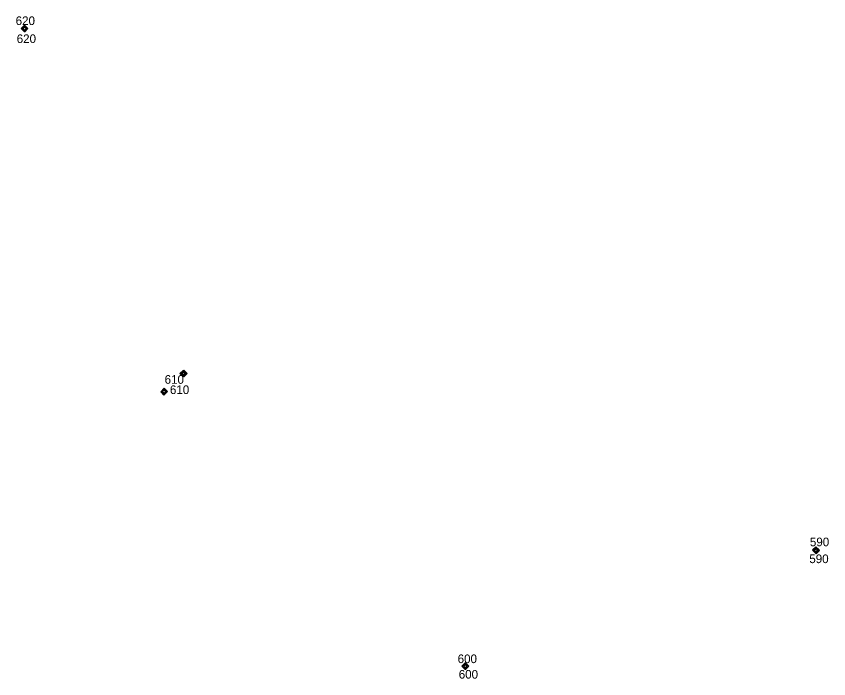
# Model space of a CAD drawing. Extents: x 3461750 to 3585707, y 5917729 to 5985917.
# Drawn here: x 3566933 to 3585707, y 5919226 to 5934529 of the extents above; entities that cross this region are included whole.
import ezdxf

# ---------------------------------------------------------------- set-up
doc = ezdxf.new("R2010")
doc.units = 0
doc.header["$LTSCALE"] = 80
doc.layers.add('13', color=7, linetype='Continuous', lineweight=13)
doc.layers.add('14', color=7, linetype='Continuous', lineweight=13)

msp = doc.modelspace()

# ---------------------------------------------------------------- linework, layer by layer
at = {"layer": '13'}
for points in [[(3567129.33, 5934317.19), (3567054.24, 5934242.1), (3567129.33, 5934167.01), (3567204.42, 5934242.1)], [(3567129.33, 5934281.79), (3567089.64, 5934242.1), (3567129.33, 5934202.41), (3567169.02, 5934242.1)], [(3570804.92, 5926351.18), (3570729.82, 5926276.09), (3570804.92, 5926201), (3570880.01, 5926276.09)], [(3570804.92, 5926315.78), (3570765.22, 5926276.09), (3570804.92, 5926236.39), (3570844.61, 5926276.09)], [(3570345.78, 5925929.6), (3570270.7, 5925854.51), (3570345.78, 5925779.42), (3570420.88, 5925854.51)], [(3570345.78, 5925894.2), (3570306.09, 5925854.51), (3570345.79, 5925814.81), (3570385.48, 5925854.51)], [(3585415.22, 5922263.68), (3585340.13, 5922188.59), (3585415.22, 5922113.5), (3585490.31, 5922188.59)], [(3585415.22, 5922228.28), (3585375.53, 5922188.59), (3585415.22, 5922148.89), (3585454.91, 5922188.59)], [(3577313.46, 5919592.1), (3577238.37, 5919517.01), (3577313.46, 5919441.92), (3577388.55, 5919517.01)], [(3577313.46, 5919556.7), (3577273.77, 5919517.01), (3577313.46, 5919477.31), (3577353.15, 5919517.01)]]:
    msp.add_lwpolyline(points, close=True, dxfattribs=at)
at = {"layer": '14'}
for points in [[(3567120.25, 5934322.08), (3567045.16, 5934246.99), (3567120.25, 5934171.9), (3567195.34, 5934246.99)], [(3567120.25, 5934286.68), (3567080.56, 5934246.99), (3567120.25, 5934207.29), (3567159.94, 5934246.99)], [(3570785.97, 5926348.44), (3570710.88, 5926273.35), (3570785.97, 5926198.26), (3570861.06, 5926273.35)], [(3570785.97, 5926313.04), (3570746.28, 5926273.35), (3570785.97, 5926233.66), (3570825.66, 5926273.35)], [(3570354.57, 5925939.46), (3570279.48, 5925864.37), (3570354.57, 5925789.28), (3570429.66, 5925864.37)], [(3570354.57, 5925904.06), (3570314.88, 5925864.37), (3570354.57, 5925824.68), (3570394.27, 5925864.37)], [(3585409.36, 5922275.1), (3585334.27, 5922200.01), (3585409.36, 5922124.92), (3585484.45, 5922200.01)], [(3585409.36, 5922239.7), (3585369.67, 5922200.01), (3585409.36, 5922160.32), (3585449.05, 5922200.01)], [(3577306.92, 5919590.43), (3577231.83, 5919515.34), (3577306.92, 5919440.25), (3577382.01, 5919515.34)], [(3577306.92, 5919555.04), (3577267.22, 5919515.34), (3577306.92, 5919475.65), (3577346.61, 5919515.34)]]:
    msp.add_lwpolyline(points, close=True, dxfattribs=at)

# ---------------------------------------------------------------- texts
at = {"layer": '13'}
for s, p in [('620', (3566943.8, 5933909.8)), ('610', (3570483.6, 5925802.7)), ('590', (3585257.6, 5921896.7)), ('600', (3577157.1, 5919228.8))]:
    msp.add_text(s, height=200, dxfattribs=at).set_placement(p)
at = {"layer": '14'}
for s, p in [('620', (3566919.4, 5934325.8)), ('610', (3570361.3, 5926039.3)), ('590', (3585270.8, 5922285.8)), ('600', (3577132.2, 5919587.2))]:
    msp.add_text(s, height=200, dxfattribs=at).set_placement(p)

doc.saveas('drawing.dxf')
